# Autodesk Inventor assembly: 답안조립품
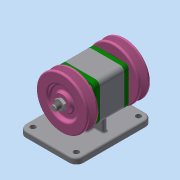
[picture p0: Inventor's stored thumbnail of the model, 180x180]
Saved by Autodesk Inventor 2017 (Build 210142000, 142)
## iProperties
Part Number: 답안조립품
Material: 일반
Document SubType Name: Assembly
Designer: 7-1
Author: 7-1
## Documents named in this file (10)
- C:\Users\7-1\Desktop\701106V1058\답안조립품.iam
- C:\Users\7-1\Desktop\701106V1058\본체.ipt
- C:\Users\7-1\Desktop\701106V1058\축.ipt
- C:\Users\7-1\Desktop\701106V1058\키 5 x 5 x 12.ipt
- C:\Users\7-1\Desktop\701106V1058\베어링 6004.ipt
- C:\Users\7-1\Desktop\701106V1058\커버.ipt
- C:\Users\7-1\Desktop\701106V1058\오일 실 17 30 5.ipt
- C:\Users\7-1\Desktop\701106V1058\볼트 M4.ipt
- C:\Users\7-1\Desktop\701106V1058\V-벨트풀리.ipt
- C:\Users\7-1\Desktop\701106V1058\너트 M10x1.ipt
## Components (2 placed, 1 different names)
1. V-벨트풀리:1
2. V-벨트풀리:2
